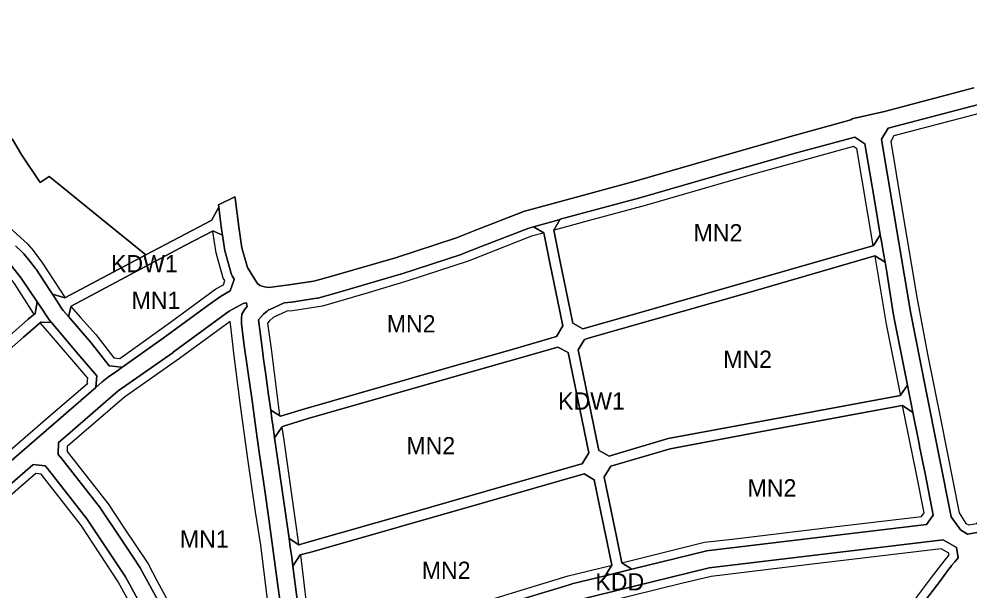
# Model space of a CAD drawing. Extents: x -284239 to -281592, y 34477 to 37267.
# Drawn here: x -283094 to -282544, y 35315 to 35646 of the extents above; entities that cross this region are included whole.
import ezdxf

# ---------------------------------------------------------------- set-up
doc = ezdxf.new("R2010")
doc.units = 0
for name, color, linetype in [('linie_rozgraniczajace', 7, 'Continuous'), ('linie_zabudowy_nieprzekraczalne', 7, 'Continuous'), ('oznaczenia_przeznaczen', 7, 'Continuous')]:
    doc.layers.add(name, color=color, linetype=linetype)

msp = doc.modelspace()

# ---------------------------------------------------------------- linework, layer by layer
at = {"layer": 'linie_rozgraniczajace'}
for points in [[(-283122.401, 35370.041), (-283092.511, 35395.841), (-283074.122, 35411.847), (-283049.517, 35433.096), (-283045.855, 35436.258), (-283043.093, 35438.643), (-283041.738, 35439.478), (-283040.283, 35440.507), (-283038.765, 35441.581), (-283034.614, 35444.517), (-283010.624, 35461.483), (-282984.677, 35480.528), (-282977.502, 35485.747), (-282971.756, 35488.886), (-282969.499, 35495.532), (-282969.458, 35495.694), (-282970.673, 35497.597), (-282971.078, 35498.373), (-282971.271, 35498.931), (-282974.801, 35511.457), (-282974.841, 35511.748), (-282974.937, 35512.094), (-282976.257, 35521.17), (-282976.758, 35524.62), (-282976.763, 35524.68), (-282976.771, 35524.709), (-282976.942, 35526.06), (-282977.741, 35532.338), (-282978.366, 35537.259), (-282978.548, 35538.69), (-282969.099, 35543.342), (-282969.003, 35542.832), (-282968.986, 35542.648), (-282968.957, 35542.539), (-282966.856, 35526.015), (-282965.088, 35513.856), (-282961.846, 35502.354), (-282956.141, 35493.416), (-282954.729, 35492.077), (-282951.944, 35491.238), (-282949.47, 35490.951), (-282937.799, 35492.318), (-282923.424, 35494.483), (-282912.929, 35497.355), (-282876.096, 35508.082), (-282840.905, 35519.624), (-282830.273, 35523.842), (-282802.469, 35534.668), (-282802.432, 35534.675), (-282801.983, 35534.829), (-282783.578, 35539.9), (-282737.43, 35552.362), (-282694.136, 35564.821), (-282648.858, 35577.749), (-282648.826, 35577.758), (-282612.707, 35587.764), (-282612.158, 35588.222), (-282612.073, 35588.398), (-282593.089, 35592.751), (-282593.067, 35592.733), (-282541.365, 35606.362)], [(-282541.365, 35606.362), (-282593.067, 35592.733), (-282593.089, 35592.751), (-282612.073, 35588.398), (-282612.158, 35588.222), (-282612.707, 35587.764), (-282648.826, 35577.758), (-282648.858, 35577.749), (-282694.136, 35564.821), (-282737.43, 35552.362), (-282783.578, 35539.9), (-282801.983, 35534.829), (-282802.432, 35534.675), (-282802.469, 35534.668), (-282830.273, 35523.842), (-282840.905, 35519.624), (-282876.096, 35508.082), (-282912.929, 35497.355), (-282923.424, 35494.483), (-282937.799, 35492.318), (-282949.47, 35490.951), (-282951.944, 35491.238), (-282954.729, 35492.077), (-282956.141, 35493.416), (-282961.846, 35502.354), (-282965.088, 35513.856), (-282966.856, 35526.015), (-282968.957, 35542.539), (-282968.986, 35542.648), (-282969.003, 35542.832), (-282969.099, 35543.342), (-282978.548, 35538.69), (-282978.366, 35537.259), (-282982.4, 35530.016), (-282982.468, 35529.851), (-283020.633, 35509.776), (-283020.679, 35509.813), (-283045.925, 35530.211), (-283051.157, 35534.466), (-283071.775, 35551.124), (-283076.605, 35555.029), (-283081.782, 35551.573), (-283092.471, 35567.431), (-283098.027, 35576.957)], [(-282538.845, 35596.685), (-282590.976, 35582.942), (-282594.917, 35576.583), (-282594.945, 35576.545), (-282578.266, 35477.933), (-282578.248, 35477.827), (-282569.253, 35431.856), (-282554.592, 35358.189), (-282554.568, 35358.169), (-282549.241, 35350.623), (-282545.086, 35348.256), (-282544.893, 35348.256), (-282537.511, 35349.521)], [(-282537.511, 35349.521), (-282544.893, 35348.256), (-282545.086, 35348.256), (-282549.241, 35350.623), (-282554.568, 35358.169), (-282554.592, 35358.189), (-282569.253, 35431.856), (-282578.248, 35477.827), (-282578.266, 35477.933), (-282594.945, 35576.545), (-282594.917, 35576.583), (-282590.976, 35582.942), (-282538.845, 35596.685)], [(-283098.027, 35576.957), (-283092.471, 35567.431), (-283081.782, 35551.573), (-283076.605, 35555.029), (-283071.775, 35551.124), (-283051.157, 35534.466), (-283045.925, 35530.211), (-283020.679, 35509.813), (-283067.597, 35484.813), (-283074.693, 35486.963), (-283077.051, 35490.569), (-283084.172, 35501.458), (-283084.423, 35501.791), (-283084.63, 35502.141), (-283085.634, 35503.394), (-283088.527, 35507.004), (-283091.222, 35510.367), (-283091.303, 35510.42), (-283091.353, 35510.492), (-283092.56, 35511.615), (-283096.13, 35514.935)], [(-282802.477, 35310.724), (-282774.356, 35319.339), (-282774.277, 35319.35), (-282774.084, 35319.413), (-282754.88, 35324.131), (-282739.337, 35327.949), (-282696.757, 35338.409), (-282696.418, 35338.45), (-282696.159, 35338.518), (-282568.939, 35353.762), (-282564.906, 35359.202), (-282569.71, 35383.257), (-282572.844, 35398.948), (-282572.957, 35399.51), (-282576.754, 35418.516), (-282577.757, 35423.533), (-282578.922, 35429.365), (-282579.935, 35434.433), (-282587.244, 35471.014), (-282588.06, 35476.058), (-282591.874, 35499.656), (-282592.867, 35505.477), (-282593.733, 35510.564), (-282594.752, 35516.539), (-282595.57, 35521.338), (-282598.971, 35541.299), (-282601.665, 35557.108), (-282604.564, 35574.065), (-282610.287, 35577.766), (-282646.138, 35568.127), (-282691.379, 35555.208), (-282734.716, 35542.739), (-282780.77, 35530.297), (-282780.948, 35530.252), (-282796.209, 35526.047), (-282799.08, 35525.256), (-282826.611, 35514.537), (-282837.358, 35510.273), (-282837.528, 35510.24), (-282837.644, 35510.169), (-282873.059, 35498.554), (-282873.094, 35498.548), (-282873.219, 35498.504), (-282910.184, 35487.741), (-282921.068, 35484.76), (-282921.335, 35484.724), (-282921.644, 35484.638), (-282936.391, 35482.418), (-282936.502, 35482.409), (-282936.554, 35482.396), (-282940.521, 35481.931), (-282949.195, 35477.893), (-282949.561, 35477.948), (-282950.386, 35477.232), (-282952.502, 35475.38), (-282955.413, 35472.073), (-282953.369, 35456.191), (-282952.502, 35449.451), (-282951.216, 35440.273), (-282949.592, 35428.681), (-282948.353, 35419.888), (-282947.646, 35414.871), (-282947.119, 35411.131), (-282946.763, 35408.6), (-282946.101, 35403.906), (-282943.506, 35385.487), (-282937.751, 35345.57), (-282937.035, 35340.608), (-282936.363, 35335.944), (-282936.23, 35334.916), (-282935.563, 35329.754), (-282933.055, 35310.346)], [(-283096.13, 35514.935), (-283092.56, 35511.615), (-283091.353, 35510.492), (-283091.303, 35510.42), (-283091.222, 35510.367), (-283088.527, 35507.004), (-283085.634, 35503.394), (-283084.63, 35502.141), (-283084.423, 35501.791), (-283084.172, 35501.458), (-283077.051, 35490.569), (-283074.693, 35486.963), (-283071.816, 35482.565), (-283069.172, 35478.522), (-283068.391, 35477.617), (-283065.315, 35474.055), (-283052.24, 35458.913), (-283052.176, 35458.841), (-283041.854, 35445.556), (-283041.558, 35445.516), (-283034.81, 35444.688), (-283034.614, 35444.517), (-283038.765, 35441.581), (-283040.283, 35440.507), (-283041.738, 35439.478), (-283043.093, 35438.643), (-283045.855, 35436.258), (-283049.517, 35433.096), (-283049.609, 35433.203), (-283048.926, 35439.806), (-283059.768, 35452.332), (-283075.196, 35470.539), (-283076.594, 35472.189), (-283077.753, 35473.919), (-283081.071, 35478.87), (-283083.567, 35482.594), (-283092.708, 35496.233), (-283098.436, 35503.424)], [(-283098.436, 35503.424), (-283092.708, 35496.233), (-283083.567, 35482.594), (-283084.701, 35475.893), (-283088.711, 35472.604), (-283104.997, 35457.997)], [(-282943.089, 35309.907), (-282946.701, 35337.049), (-282949.546, 35356.967), (-282951.844, 35373.383), (-282955.018, 35395.6), (-282956.918, 35409.53), (-282959.286, 35426.9), (-282961.694, 35442.66), (-282963.992, 35458.748), (-282965.196, 35470.13), (-282965.196, 35472.975), (-282965.087, 35475.492), (-282963.992, 35477.353), (-282962.017, 35480.094), (-282962.027, 35480.143), (-282962.311, 35481.672), (-282962.36, 35481.933), (-282964.392, 35481.627), (-282972.348, 35477.172), (-282976.642, 35474.02), (-283004.772, 35453.374), (-283004.831, 35453.341), (-283004.903, 35453.281), (-283036.557, 35431.075), (-283067.572, 35404.292), (-283071.166, 35401.163), (-283071.276, 35394.369), (-283071.32, 35394.224), (-283069.938, 35392.654), (-283069.909, 35392.608), (-283069.755, 35392.434), (-283046.803, 35363.131), (-283046.73, 35363.006), (-283046.581, 35362.825), (-283035.664, 35346.482), (-283027.554, 35334.272), (-283023.886, 35328.749), (-283023.75, 35328.494), (-283023.658, 35328.372), (-283009.305, 35301.979)], [(-283009.305, 35301.979), (-283023.658, 35328.372), (-283023.75, 35328.494), (-283023.886, 35328.749), (-283027.554, 35334.272), (-283035.664, 35346.482), (-283046.581, 35362.825), (-283046.73, 35363.006), (-283046.803, 35363.131), (-283069.755, 35392.434), (-283069.909, 35392.608), (-283069.938, 35392.654), (-283071.32, 35394.224), (-283071.276, 35394.369), (-283071.166, 35401.163), (-283067.572, 35404.292), (-283036.557, 35431.075), (-283004.903, 35453.281), (-283004.831, 35453.341), (-283004.772, 35453.374), (-282976.642, 35474.02), (-282972.348, 35477.172), (-282964.392, 35481.627), (-282962.36, 35481.933), (-282962.311, 35481.672), (-282962.027, 35480.143), (-282962.017, 35480.094), (-282963.992, 35477.353), (-282965.087, 35475.492), (-282965.196, 35472.975), (-282965.196, 35470.13), (-282963.992, 35458.748), (-282961.694, 35442.66), (-282959.286, 35426.9), (-282956.918, 35409.53), (-282955.018, 35395.6), (-282951.844, 35373.383), (-282949.546, 35356.967), (-282946.701, 35337.049), (-282943.089, 35309.907)], [(-283101.438, 35453.229), (-283091.364, 35462.228), (-283081.391, 35470.733), (-283075.196, 35470.539), (-283059.768, 35452.332), (-283048.926, 35439.806), (-283049.609, 35433.203), (-283049.517, 35433.096), (-283074.122, 35411.847), (-283092.511, 35395.841), (-283122.401, 35370.041)], [(-283018.159, 35297.33), (-283032.338, 35323.4), (-283043.986, 35340.938), (-283054.792, 35357.113), (-283077.539, 35386.154), (-283078.934, 35387.739), (-283078.971, 35387.739), (-283085.791, 35388.432), (-283085.962, 35388.284), (-283115.933, 35362.414)], [(-283115.933, 35362.414), (-283085.962, 35388.284), (-283085.791, 35388.432), (-283078.971, 35387.739), (-283078.934, 35387.739), (-283077.539, 35386.154), (-283054.792, 35357.113), (-283043.986, 35340.938), (-283032.338, 35323.4), (-283018.159, 35297.33)], [(-282933.055, 35310.346), (-282935.563, 35329.754), (-282931.33, 35336.192), (-282924.365, 35337.992), (-282824.617, 35366.567), (-282766.972, 35382.993), (-282761.124, 35379.541), (-282757.111, 35359.942), (-282757.095, 35359.939), (-282753.895, 35344.234), (-282753.893, 35344.223), (-282751.027, 35330.222), (-282754.88, 35324.131), (-282774.084, 35319.413), (-282774.277, 35319.35), (-282774.356, 35319.339), (-282802.477, 35310.724)], [(-282573.319, 35305.021), (-282561.18, 35320.73), (-282556.044, 35327.727), (-282554.998, 35329.151), (-282554.293, 35330.112), (-282552.538, 35332.098), (-282550.456, 35334.409), (-282551.417, 35340.364), (-282559.298, 35344.846), (-282694.667, 35328.625), (-282771.562, 35309.736)], [(-282771.562, 35309.736), (-282694.667, 35328.625), (-282559.298, 35344.846), (-282551.417, 35340.364), (-282550.456, 35334.409), (-282552.538, 35332.098), (-282554.293, 35330.112), (-282554.998, 35329.151), (-282556.044, 35327.727), (-282561.18, 35320.73), (-282573.319, 35305.021)]]:
    msp.add_lwpolyline(points, dxfattribs=at)
for points in [[(-282784.589, 35524.075), (-282780.77, 35530.297), (-282734.716, 35542.739), (-282691.379, 35555.208), (-282646.138, 35568.127), (-282610.287, 35577.766), (-282604.564, 35574.065), (-282601.665, 35557.108), (-282598.971, 35541.299), (-282595.57, 35521.338), (-282599.356, 35515.264), (-282599.401, 35515.199), (-282672.613, 35494.096), (-282741.934, 35474.318), (-282767.642, 35466.903), (-282773.452, 35470.285), (-282773.582, 35470.311), (-282777.609, 35489.98), (-282777.629, 35489.995), (-282780.828, 35505.725), (-282780.833, 35505.728)], [(-283074.693, 35486.963), (-283067.597, 35484.813), (-283020.679, 35509.813), (-283020.633, 35509.776), (-282982.468, 35529.851), (-282982.4, 35530.016), (-282978.366, 35537.259), (-282977.741, 35532.338), (-282976.942, 35526.06), (-282976.771, 35524.709), (-282976.763, 35524.68), (-282976.758, 35524.62), (-282976.257, 35521.17), (-282981.474, 35523.534), (-282981.644, 35523.607), (-282998.011, 35515.068), (-283063.893, 35480.011), (-283065.315, 35474.055), (-283068.391, 35477.617), (-283069.172, 35478.522), (-283071.816, 35482.565)], [(-282948.353, 35419.888), (-282942.786, 35416.442), (-282942.66, 35416.407), (-282928.598, 35420.74), (-282850.017, 35443.23), (-282807.287, 35455.467), (-282782.977, 35462.479), (-282779.379, 35468.711), (-282783.405, 35488.377), (-282783.442, 35488.399), (-282783.436, 35488.41), (-282786.611, 35504.074), (-282786.619, 35504.076), (-282790.386, 35522.477), (-282796.209, 35526.047), (-282780.948, 35530.252), (-282780.77, 35530.297), (-282784.589, 35524.075), (-282780.833, 35505.728), (-282780.828, 35505.725), (-282777.629, 35489.995), (-282777.609, 35489.98), (-282773.582, 35470.311), (-282773.452, 35470.285), (-282767.642, 35466.903), (-282741.934, 35474.318), (-282672.613, 35494.096), (-282599.401, 35515.199), (-282599.356, 35515.264), (-282595.57, 35521.338), (-282594.752, 35516.539), (-282593.733, 35510.564), (-282592.867, 35505.477), (-282598.818, 35509.093), (-282673.539, 35487.482), (-282763.895, 35461.685), (-282766.689, 35460.839), (-282770.42, 35454.868), (-282758.499, 35396.638), (-282758.371, 35396.598), (-282752.546, 35393.294), (-282749.343, 35394.348), (-282718.386, 35403.476), (-282645.229, 35417.102), (-282583.978, 35428.43), (-282583.878, 35428.613), (-282579.935, 35434.433), (-282578.922, 35429.365), (-282577.757, 35423.533), (-282576.754, 35418.516), (-282582.687, 35422.527), (-282582.886, 35422.581), (-282664.147, 35407.511), (-282717.196, 35397.523), (-282751.588, 35387.458), (-282755.328, 35381.252), (-282755.342, 35381.216), (-282751.326, 35361.599), (-282751.319, 35361.594), (-282748.122, 35345.847), (-282748.099, 35345.839), (-282745.196, 35331.654), (-282739.337, 35327.949), (-282754.88, 35324.131), (-282751.027, 35330.222), (-282753.893, 35344.223), (-282753.895, 35344.234), (-282757.095, 35359.939), (-282757.111, 35359.942), (-282761.124, 35379.541), (-282766.972, 35382.993), (-282824.617, 35366.567), (-282924.365, 35337.992), (-282931.33, 35336.192), (-282935.563, 35329.754), (-282936.23, 35334.916), (-282936.363, 35335.944), (-282937.035, 35340.608), (-282937.751, 35345.57), (-282932.07, 35342.094), (-282931.979, 35342.053), (-282929.524, 35342.754), (-282866.421, 35360.746), (-282812.314, 35376.29), (-282768.224, 35388.791), (-282768.161, 35388.925), (-282764.32, 35395.155), (-282776.207, 35453.217), (-282782.107, 35456.409), (-282839.037, 35440.055), (-282926.614, 35415.052), (-282940.901, 35410.554), (-282941.704, 35410.286), (-282941.86, 35410.092), (-282946.101, 35403.906), (-282946.763, 35408.6), (-282947.119, 35411.131), (-282947.646, 35414.871)], [(-282955.413, 35472.073), (-282952.502, 35475.38), (-282950.386, 35477.232), (-282949.561, 35477.948), (-282949.195, 35477.893), (-282940.521, 35481.931), (-282936.554, 35482.396), (-282936.502, 35482.409), (-282936.391, 35482.418), (-282921.644, 35484.638), (-282921.335, 35484.724), (-282921.068, 35484.76), (-282910.184, 35487.741), (-282873.219, 35498.504), (-282873.094, 35498.548), (-282873.059, 35498.554), (-282837.644, 35510.169), (-282837.528, 35510.24), (-282837.358, 35510.273), (-282826.611, 35514.537), (-282799.08, 35525.256), (-282796.209, 35526.047), (-282790.386, 35522.477), (-282786.619, 35504.076), (-282786.611, 35504.074), (-282783.436, 35488.41), (-282783.442, 35488.399), (-282783.405, 35488.377), (-282779.379, 35468.711), (-282782.977, 35462.479), (-282807.287, 35455.467), (-282850.017, 35443.23), (-282928.598, 35420.74), (-282942.66, 35416.407), (-282942.786, 35416.442), (-282948.353, 35419.888), (-282949.592, 35428.681), (-282951.216, 35440.273), (-282952.502, 35449.451), (-282953.369, 35456.191)], [(-283065.315, 35474.055), (-283063.893, 35480.011), (-282998.011, 35515.068), (-282981.644, 35523.607), (-282981.474, 35523.534), (-282976.257, 35521.17), (-282974.937, 35512.094), (-282974.841, 35511.748), (-282974.801, 35511.457), (-282971.271, 35498.931), (-282971.078, 35498.373), (-282970.673, 35497.597), (-282969.458, 35495.694), (-282969.499, 35495.532), (-282971.756, 35488.886), (-282977.502, 35485.747), (-282984.677, 35480.528), (-283010.624, 35461.483), (-283034.614, 35444.517), (-283034.81, 35444.688), (-283041.558, 35445.516), (-283041.854, 35445.556), (-283052.176, 35458.841), (-283052.24, 35458.913)], [(-282770.42, 35454.868), (-282766.689, 35460.839), (-282763.895, 35461.685), (-282673.539, 35487.482), (-282598.818, 35509.093), (-282592.867, 35505.477), (-282591.874, 35499.656), (-282588.06, 35476.058), (-282587.244, 35471.014), (-282579.935, 35434.433), (-282583.878, 35428.613), (-282583.978, 35428.43), (-282645.229, 35417.102), (-282718.386, 35403.476), (-282749.343, 35394.348), (-282752.546, 35393.294), (-282758.371, 35396.598), (-282758.499, 35396.638)], [(-283181.627, 35384.658), (-283166.18, 35399.031), (-283152.11, 35412.496), (-283144.622, 35419.515), (-283134.414, 35429.79), (-283119.94, 35444.062), (-283104.997, 35457.997), (-283088.711, 35472.604), (-283084.701, 35475.893), (-283083.567, 35482.594), (-283081.071, 35478.87), (-283077.753, 35473.919), (-283076.594, 35472.189), (-283075.196, 35470.539), (-283081.391, 35470.733), (-283091.364, 35462.228), (-283101.438, 35453.229), (-283112.217, 35442.987), (-283124.675, 35431.133), (-283137.738, 35418.003), (-283146.972, 35409.037), (-283165.072, 35391.878), (-283177.799, 35379.957)], [(-282946.101, 35403.906), (-282941.86, 35410.092), (-282941.704, 35410.286), (-282940.901, 35410.554), (-282926.614, 35415.052), (-282839.037, 35440.055), (-282782.107, 35456.409), (-282776.207, 35453.217), (-282764.32, 35395.155), (-282768.161, 35388.925), (-282768.224, 35388.791), (-282812.314, 35376.29), (-282866.421, 35360.746), (-282929.524, 35342.754), (-282931.979, 35342.053), (-282932.07, 35342.094), (-282937.751, 35345.57), (-282943.506, 35385.487)], [(-282755.342, 35381.216), (-282755.328, 35381.252), (-282751.588, 35387.458), (-282717.196, 35397.523), (-282664.147, 35407.511), (-282582.886, 35422.581), (-282582.687, 35422.527), (-282576.754, 35418.516), (-282572.957, 35399.51), (-282572.844, 35398.948), (-282569.71, 35383.257), (-282564.906, 35359.202), (-282568.939, 35353.762), (-282696.159, 35338.518), (-282696.418, 35338.45), (-282696.757, 35338.409), (-282739.337, 35327.949), (-282745.196, 35331.654), (-282748.099, 35345.839), (-282748.122, 35345.847), (-282751.319, 35361.594), (-282751.326, 35361.599)]]:
    msp.add_lwpolyline(points, close=True, dxfattribs=at)
at = {"layer": 'linie_zabudowy_nieprzekraczalne'}
for points in [[(-283355.523, 35636.02), (-283360.937, 35639.423), (-283371.388, 35646.17), (-283379.59, 35645.641), (-283426.951, 35603.109), (-283443.091, 35588.16), (-283443.355, 35585.117), (-283417.823, 35557.336), (-283402.874, 35542.122), (-283392.423, 35532.399), (-283352.735, 35498.4), (-283344.004, 35491.984), (-283327.335, 35479.151), (-283299.157, 35454.611), (-283245.579, 35410.492), (-283216.21, 35386.018), (-283206.553, 35377.022), (-283183.798, 35353.077), (-283170.437, 35336.871), (-283167.923, 35336.739), (-283147.683, 35355.921), (-283124.399, 35374.905), (-283078.759, 35414.527), (-283054.285, 35435.561)], [(-282452.498, 35611.149), (-282508.316, 35599.405), (-282545.754, 35589.681), (-282587.823, 35578.569), (-282589.543, 35575.262), (-282583.458, 35539.08), (-282574.462, 35485.303), (-282568.244, 35452.362), (-282560.571, 35414.064), (-282549.855, 35360.486), (-282546.019, 35354.4), (-282544.299, 35353.606), (-282539.669, 35354.268), (-282518.634, 35379.8), (-282507.39, 35389.457), (-282505.008, 35391.045), (-282499.055, 35393.426), (-282483.18, 35395.411)], [(-283176.532, 35581.383), (-283166.61, 35580.986), (-283159.324, 35579.495), (-283150.858, 35574.6), (-283139.216, 35563.488), (-283125.722, 35549.332), (-283088.903, 35515.874), (-283087.093, 35513.844)], [(-282609.254, 35571.094), (-282611.107, 35572.417), (-282668.918, 35556.476), (-282730.963, 35538.551), (-282762.449, 35530.084), (-282784.298, 35524.084)], [(-282599.753, 35515.132), (-282609.254, 35571.227)], [(-283063.951, 35479.915), (-283058.369, 35473.588), (-283049.522, 35463.607), (-283039.071, 35450.246), (-283035.764, 35449.849), (-283006.395, 35470.751), (-282980.069, 35490.066), (-282975.703, 35492.447), (-282974.909, 35494.96), (-282975.835, 35496.283), (-282979.936, 35510.968), (-282981.798, 35523.175)], [(-282790.727, 35522.318), (-282797.374, 35520.493), (-282834.151, 35506.073), (-282868.944, 35494.63), (-282891.962, 35487.817), (-282918.421, 35480.144), (-282935.751, 35477.365), (-282939.058, 35477.233), (-282946.863, 35473.529), (-282949.112, 35471.677), (-282950.171, 35470.222), (-282948.186, 35455.471), (-282943.182, 35416.839)], [(-283085.515, 35475.682), (-283096.618, 35493.174), (-283102.306, 35500.054), (-283118.853, 35515.634)], [(-283086.961, 35513.844), (-283080.356, 35504.918), (-283067.259, 35484.942)], [(-282583.877, 35429.01), (-282584.913, 35433.974), (-282592.057, 35469.693), (-282594.305, 35483.517), (-282598.562, 35508.914)], [(-283054.549, 35435.429), (-283054.285, 35438.339), (-283076.296, 35464.25), (-283081.546, 35470.258)], [(-282971.734, 35471.246), (-283001.235, 35449.716), (-283032.986, 35427.491), (-283066.191, 35398.916), (-283066.191, 35395.94), (-283042.511, 35365.777), (-283033.118, 35351.688), (-283019.359, 35331.051), (-283014.2, 35321.393), (-283003.088, 35300.822)], [(-282949.112, 35300.986), (-282954.139, 35341.732), (-282957.182, 35361.047), (-282961.548, 35391.739), (-282965.913, 35422.563), (-282969.618, 35452.858), (-282971.47, 35468.336), (-282971.734, 35471.114)], [(-282744.97, 35331.72), (-282742.869, 35332.241), (-282697.361, 35343.486), (-282681.354, 35345.272), (-282622.484, 35352.35), (-282571.816, 35358.303), (-282570.228, 35360.552), (-282574.859, 35383.769), (-282582.687, 35422.527)], [(-282941.992, 35409.96), (-282940.778, 35402.621), (-282932.202, 35342.358)], [(-283081.14, 35382.909), (-283084.315, 35383.174), (-283111.302, 35359.89), (-283122.812, 35350.63), (-283135.776, 35339.848), (-283146.227, 35329.529), (-283154.165, 35322.65), (-283169.379, 35307.767), (-283212.373, 35275.422), (-283230.233, 35261.663), (-283230.762, 35258.885), (-283213.299, 35235.47), (-283197.028, 35210.202), (-283194.117, 35205.109), (-283190.413, 35193.864), (-283186.841, 35177.724), (-283184.734, 35159.504)], [(-283102.439, 35117.135), (-283053.623, 35138.169), (-283044.098, 35142.601), (-283025.313, 35154.507), (-283008.644, 35165.355), (-282990.784, 35178.584), (-282983.111, 35183.611), (-282981.789, 35187.382), (-282990.652, 35215.56), (-282998.854, 35238.512), (-283007.453, 35260.208), (-283018.566, 35286.336), (-283023.725, 35297.052), (-283036.557, 35320.533), (-283057.856, 35352.945), (-283059.841, 35355.458), (-283081.272, 35382.975)], [(-282601.978, 35263.251), (-282592.85, 35280.449), (-282578.166, 35306.841), (-282565.995, 35323.113), (-282557.264, 35334.226), (-282555.941, 35335.813), (-282555.941, 35337.136), (-282560.306, 35339.65), (-282573.271, 35338.128), (-282638.094, 35330.389), (-282693.392, 35323.775), (-282710.59, 35319.607), (-282769.195, 35305.188), (-282780.705, 35301.682), (-282828.991, 35286.997), (-282863.387, 35276.282), (-282874.103, 35272.313)], [(-282931.144, 35336.141), (-282922.522, 35262.986), (-282909.028, 35279.655), (-282906.25, 35281.64), (-282868.547, 35295.729), (-282808.354, 35314.183), (-282776.207, 35323.973), (-282751.618, 35330.071)]]:
    msp.add_lwpolyline(points, dxfattribs=at)

# ---------------------------------------------------------------- texts
at = {"layer": 'oznaczenia_przeznaczen'}
for s, p in [('MN2', (-282703.637, 35517.501)), ('KDW1', (-283040.806, 35499.644)), ('MN1', (-283028.873, 35478.453)), ('MN2', (-282881.198, 35464.867)), ('MN2', (-282686.512, 35444.373)), ('KDW1', (-282782.041, 35420.183)), ('MN2', (-282869.844, 35394.335)), ('MN2', (-282672.383, 35369.961)), ('MN1', (-283000.929, 35340.393)), ('MN2', (-282860.945, 35322.266)), ('KDD', (-282760.46, 35315.611))]:
    msp.add_text(s, height=10, dxfattribs=at).set_placement(p)

doc.saveas('drawing.dxf')
